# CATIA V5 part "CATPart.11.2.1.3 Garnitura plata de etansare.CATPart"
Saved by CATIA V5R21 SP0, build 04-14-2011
Part number: Garnitura plata de etanşare.1
Bounding box of the stored display mesh (mm): x -14 to 14, y -14 to 14, z 0 to 3
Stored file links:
  C:\Users\MIRCEA\Desktop\MOM\Mogan\model\CATPart.11.2.1.3 Garnitura plata de etansare.CATPart
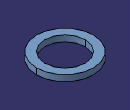
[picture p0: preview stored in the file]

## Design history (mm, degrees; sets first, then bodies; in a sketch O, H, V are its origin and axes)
Parameters
  Di = 20 mm
  De = 28 mm
  h = 3 mm
AxisSystem1: origin (0, 0, 0), X (1, 0, 0), Y (0, 1, 0), Z (0, 0, 1)
Body1 (main body)
  Sketch1 on xy-plane, origin (0, 0, 0), H (1, 0, 0), V (0, 1, 0)
    circle A1 centre (0, 0) radius 10
    circle A2 centre (0, 0) radius 14
    radius A1 = 10 {= Di/2}
    radius A2 = 14 {= De/2}
  Pad1: profile Sketch1, direction (0, 0, 1), length 3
